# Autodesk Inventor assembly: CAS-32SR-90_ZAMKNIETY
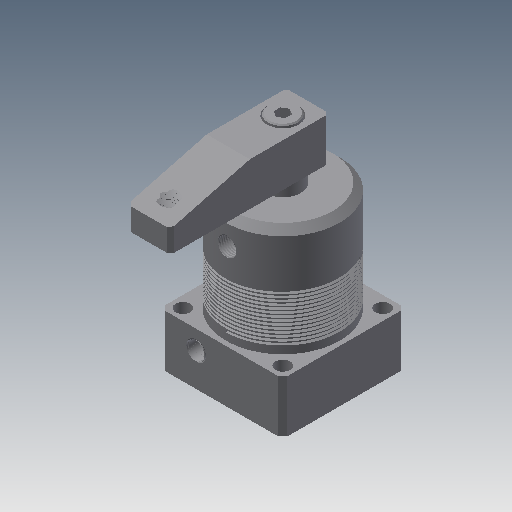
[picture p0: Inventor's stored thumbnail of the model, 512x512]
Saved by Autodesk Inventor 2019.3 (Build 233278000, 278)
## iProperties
Created: 2010-02
Part Number: CAS-32SR-90_ZAMKNIETY
Material: Ogólny
Document SubType Name: Assembly
Designer: CADENGINEERING4
Sending System: PRO/ENGINEER BY PARAMETRIC TECHNOLOGY CORPORATION, 2007170
Preprocessor: PRO/ENGINEER BY PARAMETRIC TECHNOLOGY CORPORATION, 2007170
Title: CAS-32S_ASM
Author: Administrator
Revision Number: 2LAST_VERSION
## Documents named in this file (7)
- D:\Vault_2016\Projekty\STRONA\Pneumatic\Line ; Pipe connecct - type\cas-32s_asm\CAS-32SR-90_ZAMKNIETY.iam
- D:\Vault_2016\Projekty\STRONA\Pneumatic\Line ; Pipe connecct - type\cas-32s_asm\CAS-32BT.ipt
- D:\Vault_2016\Projekty\STRONA\Pneumatic\Line ; Pipe connecct - type\cas-32s_asm\CAS-32SHSG.ipt
- D:\Vault_2016\Projekty\STRONA\Pneumatic\Line ; Pipe connecct - type\cas-32s_asm\CAS-32HG.ipt
- D:\Vault_2016\Projekty\STRONA\Pneumatic\Line ; Pipe connecct - type\cas-32s_asm\CAS-32SYB.ipt
- D:\Vault_2016\Projekty\STRONA\Pneumatic\Line ; Pipe connecct - type\cas-32s_asm\M8LC.ipt
- D:\Vault_2016\Projekty\STRONA\Pneumatic\Line ; Pipe connecct - type\cas-32s_asm\M4.ipt
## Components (9 placed, 9 different names)
1. CAS-32BT_0 — Zestawiające:5, Kątowe:1, Równoległe:1
2. CAS-32SHSG_1 — Zestawiające:1, Zestawiające:2, Zestawiające:4, Zestawiające:5
3. CAS-32HG_2
4. CAS-32SYB_3 — Zestawiające:1, Zestawiające:3, Zestawiające:4, Kątowe:1, Równoległe:1
5. M8LC_4 — Zestawiające:2, Zestawiające:3
6. M4_5
7. M4_6
8. M4_7
9. M4_8
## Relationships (7: Mate 5, Angle 1, Flush 1)
- Zestawiające:1 [Mate]: CAS-32SHSG_1 ↔ CAS-32SYB_3
- Zestawiające:2 [Mate]: CAS-32SHSG_1 ↔ M8LC_4
- Zestawiające:3 [Mate]: CAS-32SYB_3 ↔ M8LC_4
- Zestawiające:4 [Mate]: CAS-32SHSG_1 ↔ CAS-32SYB_3
- Zestawiające:5 [Mate]: CAS-32BT_0 ↔ CAS-32SHSG_1
- Kątowe:1 [Angle]: CAS-32BT_0 ↔ CAS-32SYB_3
- Równoległe:1 [Flush]: CAS-32BT_0 ↔ CAS-32SYB_3
